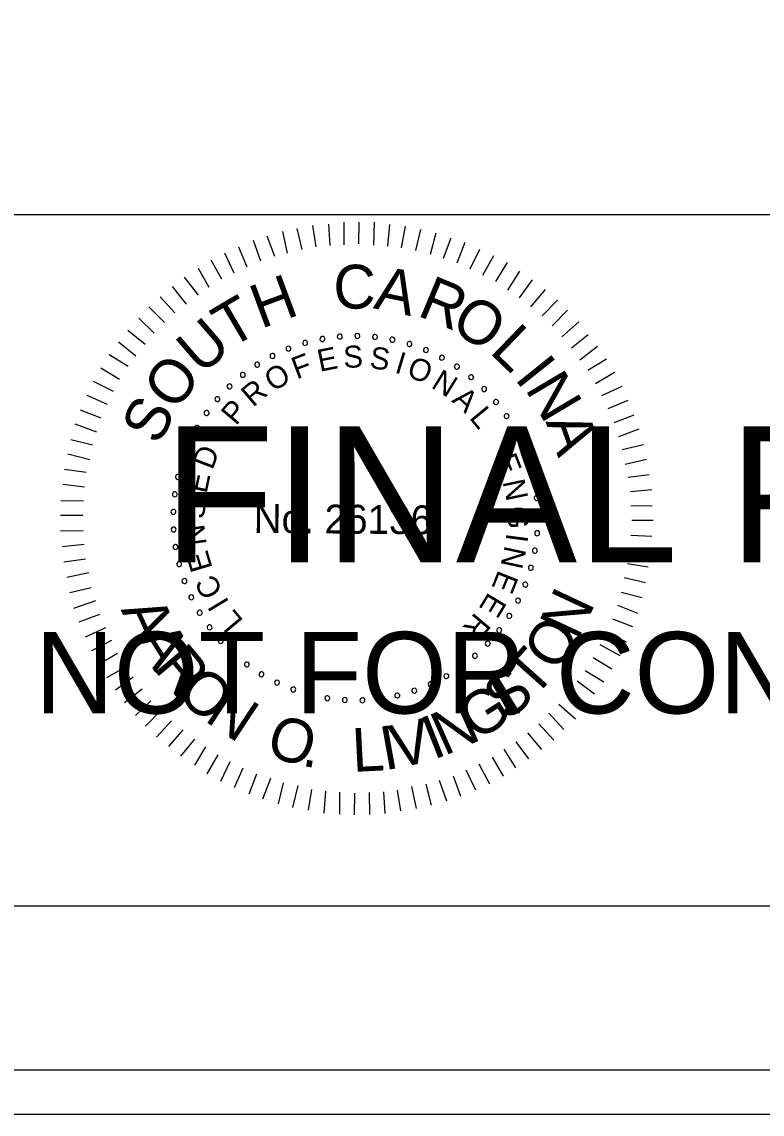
# Model space of a CAD drawing. Extents: x 967 to 1326, y 964 to 3144.
# Drawn here: x 1170.56 to 1189.3, y 2923.72 to 2951.36 of the extents above; entities that cross this region are included whole.
import ezdxf

# ---------------------------------------------------------------- set-up
doc = ezdxf.new("R2010")
doc.units = 0
for name, color, linetype in [('RD_SHT_Bndy', 7, 'Continuous'), ('RD_SHT_IplotShp', 7, 'Continuous'), ('RD_SHT_Misc1', 7, 'Continuous'), ('RD_SHT_Misc2', 7, 'Continuous'), ('RD_Sketch1', 7, 'Continuous')]:
    doc.layers.add(name, color=color, linetype=linetype)

msp = doc.modelspace()

# ---------------------------------------------------------------- linework, layer by layer
at = {"layer": 'RD_SHT_Bndy'}
for p, q in [((996.114, 2946.486), (1323.886, 2946.486)), ((1323.886, 2928.983), (996.114, 2928.983))]:
    msp.add_line(p, q, dxfattribs=at)
at = {"layer": 'RD_SHT_IplotShp'}
for points in [[(967.409, 2923.72), (1326.285, 2923.72), (1326.285, 3143.72), (967.409, 3143.72)], [(988.525, 2924.84), (1326.285, 2924.84), (1326.285, 3142.6), (988.525, 3142.6)]]:
    msp.add_lwpolyline(points, close=True, dxfattribs=at)
at = {"layer": 'RD_SHT_Misc1'}
for p, q in [((1177.657, 2945.597), (1177.53, 2946.128)), ((1178.01, 2945.663), (1177.93, 2946.209)), ((1178.364, 2945.699), (1178.33, 2946.244)), ((1178.717, 2945.719), (1178.722, 2946.295)), ((1179.093, 2945.739), (1179.098, 2946.292)), ((1179.469, 2945.713), (1179.489, 2946.288)), ((1179.829, 2945.687), (1179.872, 2946.231)), ((1180.174, 2945.646), (1180.271, 2946.19)), ((1176.964, 2945.419), (1176.769, 2945.935)), ((1177.287, 2945.508), (1177.169, 2946.054)), ((1180.535, 2945.573), (1180.662, 2946.102)), ((1180.902, 2945.478), (1181.045, 2946.022)), ((1181.231, 2945.384), (1181.428, 2945.896)), ((1176.264, 2945.156), (1176.053, 2945.657)), ((1176.61, 2945.306), (1176.423, 2945.83)), ((1181.584, 2945.265), (1181.78, 2945.786)), ((1181.905, 2945.109), (1182.154, 2945.606)), ((1175.624, 2944.846), (1175.352, 2945.332)), ((1175.933, 2945.005), (1175.699, 2945.506)), ((1182.226, 2944.953), (1182.506, 2945.45)), ((1175.308, 2944.634), (1175.036, 2945.12)), ((1182.562, 2944.789), (1182.85, 2945.27)), ((1182.86, 2944.572), (1183.163, 2945.053)), ((1175.03, 2944.445), (1174.681, 2944.9)), ((1183.158, 2944.378), (1183.484, 2944.828)), ((1174.729, 2944.217), (1174.372, 2944.665)), ((1183.447, 2944.145), (1183.811, 2944.587)), ((1174.435, 2943.997), (1174.062, 2944.399)), ((1183.729, 2943.92), (1184.116, 2944.316)), ((1174.172, 2943.753), (1173.776, 2944.148)), ((1183.98, 2943.672), (1184.368, 2944.061)), ((1173.909, 2943.479), (1173.52, 2943.858)), ((1184.232, 2943.394), (1184.657, 2943.767)), ((1173.684, 2943.197), (1173.242, 2943.546)), ((1184.475, 2943.108), (1184.892, 2943.45)), ((1173.451, 2942.9), (1173.009, 2943.256)), ((1184.687, 2942.807), (1185.128, 2943.156)), ((1173.257, 2942.64), (1172.776, 2942.936)), ((1184.885, 2942.544), (1185.355, 2942.832)), ((1173.039, 2942.312), (1172.559, 2942.6)), ((1172.883, 2942.006), (1172.379, 2942.256)), ((1185.081, 2942.213), (1185.56, 2942.493)), ((1185.24, 2941.904), (1185.756, 2942.145)), ((1172.727, 2941.677), (1172.215, 2941.904)), ((1185.399, 2941.573), (1185.907, 2941.791)), ((1172.571, 2941.333), (1172.051, 2941.53)), ((1172.461, 2940.974), (1171.91, 2941.178)), ((1185.549, 2941.226), (1186.057, 2941.414)), ((1185.669, 2940.865), (1186.185, 2941.06)), ((1172.351, 2940.652), (1171.807, 2940.787)), ((1185.759, 2940.541), (1186.297, 2940.667)), ((1172.286, 2940.276), (1171.727, 2940.419)), ((1185.832, 2940.165), (1186.371, 2940.298)), ((1172.191, 2939.955), (1171.647, 2940.029)), ((1185.906, 2939.842), (1186.436, 2939.906)), ((1172.15, 2939.587), (1171.598, 2939.653)), ((1185.964, 2939.473), (1186.51, 2939.53)), ((1172.124, 2939.234), (1171.548, 2939.239)), ((1185.977, 2939.12), (1186.514, 2939.115)), ((1172.105, 2938.866), (1171.545, 2938.871)), ((1185.997, 2938.751), (1186.542, 2938.747)), ((1172.118, 2938.482), (1171.542, 2938.471)), ((1172.138, 2938.136), (1171.585, 2938.072)), ((1185.971, 2938.368), (1186.508, 2938.348)), ((1185.952, 2938.022), (1186.497, 2937.949)), ((1172.173, 2937.768), (1171.627, 2937.688)), ((1185.888, 2937.655), (1186.417, 2937.566)), ((1172.262, 2937.414), (1171.701, 2937.296)), ((1185.808, 2937.302), (1186.345, 2937.175)), ((1172.321, 2937.037), (1171.774, 2936.911)), ((1185.729, 2936.926), (1186.265, 2936.792)), ((1172.425, 2936.707), (1171.871, 2936.519)), ((1185.634, 2936.597), (1186.146, 2936.401)), ((1172.53, 2936.36), (1172.007, 2936.173)), ((1185.508, 2936.253), (1186.013, 2936.057)), ((1172.681, 2936.029), (1172.165, 2935.788)), ((1185.352, 2935.924), (1185.857, 2935.675)), ((1172.831, 2935.705), (1172.323, 2935.441)), ((1172.982, 2935.374), (1172.497, 2935.094)), ((1185.188, 2935.603), (1185.7, 2935.33)), ((1185.024, 2935.274), (1185.498, 2934.987)), ((1173.194, 2935.042), (1172.709, 2934.762)), ((1184.822, 2934.946), (1185.288, 2934.658)), ((1173.384, 2934.78), (1172.936, 2934.453)), ((1184.62, 2934.687), (1185.055, 2934.353)), ((1173.612, 2934.478), (1173.164, 2934.129)), ((1184.403, 2934.389), (1184.814, 2934.033)), ((1173.832, 2934.177), (1173.437, 2933.812)), ((1184.155, 2934.092), (1184.574, 2933.72)), ((1174.091, 2933.945), (1173.689, 2933.541)), ((1183.899, 2933.864), (1184.28, 2933.454)), ((1174.35, 2933.674), (1173.97, 2933.263)), ((1174.64, 2933.442), (1174.275, 2933.022)), ((1183.644, 2933.597), (1184.024, 2933.18)), ((1174.937, 2933.209), (1174.58, 2932.782)), ((1183.065, 2933.141), (1183.384, 2932.709)), ((1183.358, 2933.37), (1183.715, 2932.944)), ((1175.212, 2933.014), (1174.932, 2932.549)), ((1182.764, 2932.952), (1183.059, 2932.482)), ((1175.525, 2932.812), (1175.245, 2932.331)), ((1175.83, 2932.633), (1175.588, 2932.136)), ((1182.124, 2932.581), (1182.396, 2932.08)), ((1182.463, 2932.755), (1182.743, 2932.269)), ((1176.159, 2932.477), (1175.94, 2931.98)), ((1176.503, 2932.321), (1176.307, 2931.816)), ((1181.8, 2932.431), (1182.041, 2931.93)), ((1176.855, 2932.211), (1176.651, 2931.69)), ((1177.177, 2932.1), (1177.05, 2931.572)), ((1177.545, 2932.036), (1177.409, 2931.484)), ((1180.791, 2932.07), (1180.926, 2931.54)), ((1181.122, 2932.175), (1181.31, 2931.652)), ((1181.476, 2932.28), (1181.664, 2931.771)), ((1177.897, 2931.933), (1177.808, 2931.412)), ((1178.25, 2931.892), (1178.207, 2931.34)), ((1178.603, 2931.866), (1178.598, 2931.313)), ((1178.978, 2931.84), (1178.974, 2931.295)), ((1179.355, 2931.86), (1179.365, 2931.307)), ((1179.715, 2931.88), (1179.749, 2931.327)), ((1180.061, 2931.915), (1180.149, 2931.393)), ((1180.423, 2932.012), (1180.541, 2931.458))]:
    msp.add_line(p, q, dxfattribs=at)
for centre, start, end in [((1178.168, 2943.337), 10.6038, 190.6038), ((1178.609, 2943.397), 5.0653, 185.0653), ((1178.609, 2943.397), 185.0653, 5.0653), ((1179.055, 2943.414), 359.5268, 179.5268), ((1179.055, 2943.414), 179.5268, 359.5268), ((1179.5, 2943.388), 353.9884, 173.9884), ((1179.5, 2943.388), 173.9884, 353.9884), ((1179.94, 2943.319), 348.4499, 168.4499), ((1177.312, 2943.091), 21.6807, 201.6807), ((1177.312, 2943.091), 201.6807, 21.6807), ((1177.734, 2943.235), 16.1422, 196.1422), ((1177.734, 2943.235), 196.1422, 16.1422), ((1178.168, 2943.337), 190.6038, 10.6038), ((1179.94, 2943.319), 168.4499, 348.4499), ((1180.372, 2943.208), 162.9114, 342.9114), ((1180.372, 2943.208), 342.9114, 162.9114), ((1180.79, 2943.056), 337.373, 157.373), ((1176.906, 2942.908), 27.2191, 207.2191), ((1176.906, 2942.908), 207.2191, 27.2191), ((1180.79, 2943.056), 157.373, 337.373), ((1181.193, 2942.864), 151.8345, 331.8345), ((1181.193, 2942.864), 331.8345, 151.8345), ((1176.52, 2942.686), 32.7576, 212.7576), ((1176.52, 2942.686), 212.7576, 32.7576), ((1181.574, 2942.634), 146.2961, 326.2961), ((1181.574, 2942.634), 326.2961, 146.2961), ((1176.156, 2942.428), 38.2961, 218.2961), ((1176.156, 2942.428), 218.2961, 38.2961), ((1181.932, 2942.368), 140.7576, 320.7576), ((1181.932, 2942.368), 320.7576, 140.7576), ((1175.82, 2942.135), 43.8345, 223.8345), ((1175.82, 2942.135), 223.8345, 43.8345), ((1182.263, 2942.069), 135.2191, 315.2191), ((1182.263, 2942.069), 315.2191, 135.2191), ((1175.513, 2941.812), 49.373, 229.373), ((1175.513, 2941.812), 229.373, 49.373), ((1182.563, 2941.74), 129.6807, 309.6807), ((1182.563, 2941.74), 309.6807, 129.6807), ((1175.239, 2941.461), 54.9114, 234.9114), ((1175.239, 2941.461), 234.9114, 54.9114), ((1182.83, 2941.383), 124.1422, 304.1422), ((1182.83, 2941.383), 304.1422, 124.1422), ((1175, 2941.085), 60.4499, 240.4499), ((1175, 2941.085), 240.4499, 60.4499), ((1183.061, 2941.002), 118.6038, 298.6038), ((1183.061, 2941.002), 298.6038, 118.6038), ((1174.798, 2940.687), 65.9884, 245.9884), ((1174.798, 2940.687), 245.9884, 65.9884), ((1183.255, 2940.601), 113.0653, 293.0653), ((1183.255, 2940.601), 293.0653, 113.0653), ((1174.636, 2940.272), 71.5268, 251.5268), ((1174.636, 2940.272), 251.5268, 71.5268), ((1183.408, 2940.182), 107.5268, 287.5268), ((1183.408, 2940.182), 287.5268, 107.5268), ((1174.514, 2939.843), 77.0653, 257.0653), ((1174.514, 2939.843), 257.0653, 77.0653), ((1183.521, 2939.751), 101.9884, 281.9884), ((1183.521, 2939.751), 281.9884, 101.9884), ((1174.435, 2939.405), 82.6038, 262.6038), ((1174.435, 2939.405), 262.6038, 82.6038), ((1183.592, 2939.311), 96.4499, 276.4499), ((1183.592, 2939.311), 276.4499, 96.4499), ((1174.398, 2938.961), 88.1422, 268.1422), ((1174.398, 2938.961), 268.1422, 88.1422), ((1183.619, 2938.866), 90.9114, 270.9114), ((1183.619, 2938.866), 270.9114, 90.9114), ((1174.404, 2938.515), 93.6807, 273.6807), ((1174.404, 2938.515), 273.6807, 93.6807), ((1183.604, 2938.421), 85.373, 265.373), ((1183.604, 2938.421), 265.373, 85.373), ((1174.453, 2938.072), 99.2191, 279.2191), ((1174.453, 2938.072), 279.2191, 99.2191), ((1183.546, 2937.979), 79.8345, 259.8345), ((1183.546, 2937.979), 259.8345, 79.8345), ((1174.545, 2937.636), 104.7576, 284.7576), ((1174.545, 2937.636), 284.7576, 104.7576), ((1183.445, 2937.545), 74.2961, 254.2961), ((1183.445, 2937.545), 254.2961, 74.2961), ((1174.678, 2937.211), 110.2961, 290.2961), ((1174.678, 2937.211), 290.2961, 110.2961), ((1183.303, 2937.122), 68.7576, 248.7576), ((1183.303, 2937.122), 248.7576, 68.7576), ((1174.852, 2936.8), 115.8345, 295.8345), ((1174.852, 2936.8), 295.8345, 115.8345), ((1183.121, 2936.716), 63.2191, 243.2191), ((1183.121, 2936.716), 243.2191, 63.2191), ((1175.065, 2936.409), 121.373, 301.373), ((1175.065, 2936.409), 301.373, 121.373), ((1182.9, 2936.328), 57.6807, 237.6807), ((1182.9, 2936.328), 237.6807, 57.6807), ((1175.314, 2936.039), 126.9114, 306.9114), ((1175.314, 2936.039), 306.9114, 126.9114), ((1182.643, 2935.964), 52.1422, 232.1422), ((1182.643, 2935.964), 232.1422, 52.1422), ((1175.598, 2935.696), 132.4499, 312.4499), ((1175.598, 2935.696), 312.4499, 132.4499), ((1182.353, 2935.627), 46.6038, 226.6038), ((1182.353, 2935.627), 226.6038, 46.6038), ((1175.914, 2935.381), 137.9884, 317.9884), ((1175.914, 2935.381), 317.9884, 137.9884), ((1182.03, 2935.319), 41.0653, 221.0653), ((1182.03, 2935.319), 221.0653, 41.0653), ((1176.258, 2935.099), 143.5268, 323.5268), ((1176.258, 2935.099), 323.5268, 143.5268), ((1181.68, 2935.043), 35.5268, 215.5268), ((1181.68, 2935.043), 215.5268, 35.5268), ((1176.629, 2934.851), 149.0653, 329.0653), ((1176.629, 2934.851), 329.0653, 149.0653), ((1181.305, 2934.803), 29.9884, 209.9884), ((1181.305, 2934.803), 209.9884, 29.9884), ((1177.021, 2934.639), 154.6038, 334.6038), ((1177.021, 2934.639), 334.6038, 154.6038), ((1177.432, 2934.467), 340.1422, 160.1422), ((1180.908, 2934.6), 24.4499, 204.4499), ((1180.908, 2934.6), 204.4499, 24.4499), ((1177.432, 2934.467), 160.1422, 340.1422), ((1177.858, 2934.335), 165.6807, 345.6807), ((1177.858, 2934.335), 345.6807, 165.6807), ((1178.294, 2934.245), 351.2191, 171.2191), ((1178.294, 2934.245), 171.2191, 351.2191), ((1178.737, 2934.198), 356.7576, 176.7576), ((1179.183, 2934.193), 2.2961, 182.2961), ((1179.627, 2934.232), 7.8345, 187.8345), ((1179.627, 2934.232), 187.8345, 7.8345), ((1180.065, 2934.313), 13.373, 193.373), ((1180.065, 2934.313), 193.373, 13.373), ((1180.494, 2934.436), 18.9114, 198.9114), ((1180.494, 2934.436), 198.9114, 18.9114), ((1178.737, 2934.198), 176.7576, 356.7576), ((1179.183, 2934.193), 182.2961, 2.2961)]:
    msp.add_arc(centre, 0.0627, start, end, dxfattribs=at)
at = {"layer": 'RD_Sketch1'}
msp.add_lwpolyline([(967.409, 2923.72), (1326.285, 2923.72), (1326.285, 3143.72), (967.409, 3143.72)], close=True, dxfattribs=at)

# ---------------------------------------------------------------- texts
at = {"layer": 'RD_SHT_Misc1'}
for s, height, rotation, p in [('C', 1.11, 359.5482, (1178.442, 2944.108)), ('A', 1.11, 348.1981, (1179.439, 2944.115)), ('H', 1.11, 20.3637, (1176.614, 2943.587)), ('R', 1.11, 337.4344, (1180.541, 2943.937)), ('T', 1.11, 30.4992, (1175.828, 2943.072)), ('O', 1.108, 326.5869, (1181.366, 2943.609)), ('U', 1.11, 40.8022, (1175.102, 2942.403)), ('L', 1.11, 315.9488, (1182.373, 2943.003)), ('E', 0.557, 11.4103, (1178.103, 2942.503)), ('S', 0.557, 2.208, (1178.709, 2942.601)), ('S', 0.557, 352.6608, (1179.346, 2942.599)), ('O', 1.11, 52.0267, (1174.435, 2941.474)), ('F', 0.557, 20.6127, (1177.52, 2942.309)), ('I', 0.557, 343.1136, (1179.975, 2942.491)), ('O', 0.557, 338.4392, (1180.274, 2942.401)), ('I', 1.11, 308.6613, (1183.011, 2942.338)), ('O', 0.557, 30.8477, (1176.917, 2941.987)), ('N', 0.557, 328.2042, (1180.896, 2942.12)), ('N', 1.11, 300.7037, (1183.285, 2942.075)), ('R', 0.557, 40.3949, (1176.415, 2941.594)), ('A', 0.557, 318.657, (1181.424, 2941.762)), ('S', 1.108, 63.2511, (1174.029, 2940.619)), ('P', 0.557, 49.9421, (1175.985, 2941.124)), ('L', 0.557, 309.4546, (1181.869, 2941.339)), ('A', 1.11, 289.4792, (1183.814, 2941.243)), ('D', 0.557, 69.0364, (1175.386, 2940.003)), ('E', 0.557, 291.049, (1182.53, 2940.307)), ('E', 0.557, 78.2388, (1175.238, 2939.407)), ('N', 0.557, 281.8466, (1182.728, 2939.726)), ('S', 0.557, 87.786, (1175.187, 2938.772)), ('No. 26136', 0.7311, 359.5268, (1176.429, 2938.43)), ('G', 0.557, 272.2995, (1182.833, 2939.097)), ('N', 0.557, 97.3332, (1175.242, 2938.137)), ('I', 0.557, 262.4084, (1182.83, 2938.437)), ('E', 0.557, 106.5355, (1175.394, 2937.541)), ('N', 0.557, 257.7339, (1182.789, 2938.127)), ('C', 0.557, 116.4266, (1175.661, 2936.938)), ('E', 0.557, 248.1867, (1182.628, 2937.511)), ('N', 1.105, 64.8922, (1184.632, 2935.684)), ('I', 0.557, 121.1011, (1175.823, 2936.67)), ('E', 0.557, 238.9844, (1182.378, 2936.949)), ('A', 1.105, 294.7297, (1173.062, 2936.486)), ('L', 0.557, 129.9595, (1176.187, 2936.204)), ('R', 0.557, 229.782, (1182.041, 2936.435)), ('O', 1.105, 56.2059, (1184.102, 2934.874)), ('A', 1.105, 302.2892, (1173.414, 2935.72)), ('R', 1.105, 309.8487, (1173.865, 2935.007)), ('T', 1.105, 48.2685, (1183.515, 2934.211)), ('O', 1.105, 317.7861, (1174.434, 2934.33)), ('S', 1.105, 40.3311, (1182.842, 2933.636)), ('N', 1.105, 326.4725, (1175.158, 2933.686)), ('G', 1.105, 32.0198, (1182.059, 2933.14)), ('N', 1.105, 24.0824, (1181.252, 2932.776)), ('O', 1.105, 342.3472, (1176.697, 2932.82)), ('V', 1.105, 12.7741, (1180.033, 2932.457)), ('I', 1.105, 21.4605, (1180.976, 2932.681)), ('L', 1.105, 2.9677, (1178.943, 2932.379)), ('I', 1.105, 10.1523, (1179.743, 2932.418)), ('.', 1.105, 351.0336, (1177.623, 2932.536))]:
    msp.add_text(s, height=height, rotation=rotation, dxfattribs=at).set_placement(p)
at = {"layer": 'RD_SHT_Misc2'}
for s, height, p in [('FINAL PLANS', 3.4375, (1174.145, 2937.685)), ('NOT FOR CONSTRUCTION', 2.0625, (1170.901, 2933.86))]:
    msp.add_text(s, height=height, dxfattribs=at).set_placement(p)

doc.saveas('drawing.dxf')
